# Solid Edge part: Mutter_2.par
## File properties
Sűrűség: 0,000 kg/m^3
Pontosság: 0,990
Author: ahadarics
Last saved by: ahadarics
Revision: 76
Username: ahadarics
Dokumentum tartalom típus: 0
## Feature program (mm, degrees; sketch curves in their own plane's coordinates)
base feature "unnamed BaseFeature 1"
thread "unnamed Thread 1"
chamfer "unnamed Chamfer 1"
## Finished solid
Body 1: solid body, 13 faces, 24 edges, 12 vertices.
  Faces by surface: plane 8, cone 4, cylinder 1
  Edges by curve: spline 12, circle 6, line 6
Bounding box of the edges (mm): 25.403 x 22.000 x 6.000, from (-12.7017, -11, -3) to (12.7017, 11, 3).
Cylindrical faces by radius (mm): R7.188 x1
Conical faces (half-angle, radius in mm at the cone's reference point): 45 deg R7.188 x1, 45 deg R8.188 x1, 75 deg R12.75 x2
Planar faces by outward normal: +y 1, +z 1, -y 1, -z 1, oblique 4
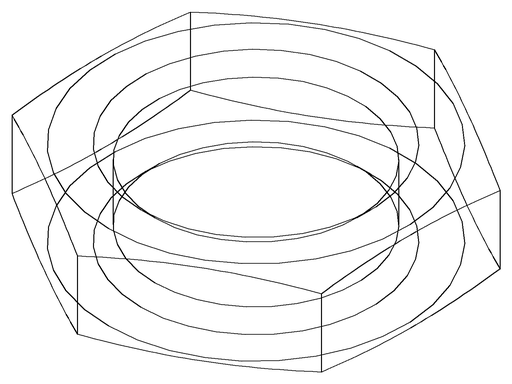
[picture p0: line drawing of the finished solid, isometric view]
